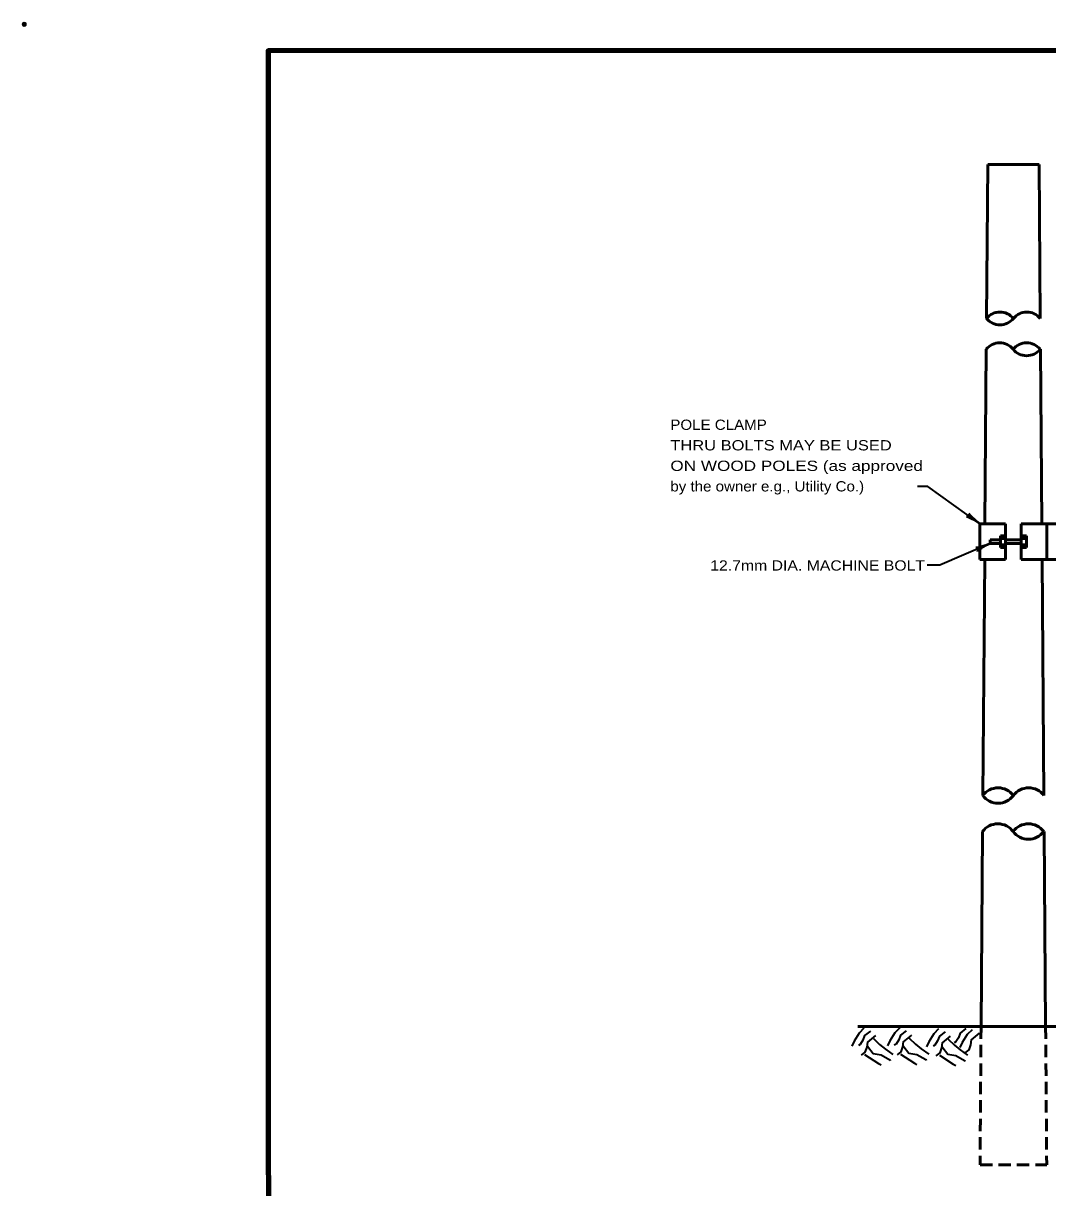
# Model space of a CAD drawing. Extents: x -421 to 434, y -46 to 498.
# Drawn here: x -421.4 to -181.8, y 225.9 to 498.2 of the extents above; entities that cross this region are included whole.
import ezdxf
from ezdxf.enums import TextEntityAlignment as Align

# ---------------------------------------------------------------- set-up
doc = ezdxf.new("R2010")
doc.units = 0
doc.header["$LTSCALE"] = 0.96
doc.header["$PDMODE"] = 32
doc.header["$PDSIZE"] = 0.48
doc.linetypes.add('MEDIUM_DASHED', pattern=[4.5, 3, -1.5])
doc.layers.add('1', color=7, linetype='Continuous', lineweight=53)

msp = doc.modelspace()

# ---------------------------------------------------------------- linework, layer by layer
at = {"layer": '1'}
for p, q in [((-195.7996, 465.1862), (-196.0765, 429.1862)), ((-195.7996, 465.1862), (-183.7996, 465.1862)), ((-183.7996, 465.1862), (-183.5226, 429.1862)), ((-196.1319, 421.9862), (-196.4457, 381.1862)), ((-183.4673, 421.9862), (-183.1534, 381.1862)), ((-191.6458, 381.1862), (-197.6458, 381.1862)), ((-197.6458, 381.1862), (-197.6458, 372.7862)), ((-191.6458, 381.1862), (-191.6458, 372.7862)), ((-187.9464, 381.1862), (-187.9464, 372.7862)), ((-187.9464, 381.1862), (-178.3464, 381.1862)), ((-181.9464, 381.1862), (-181.9464, 372.7862)), ((-192.8458, 377.4362), (-195.2458, 377.4362)), ((-195.2458, 377.4362), (-195.2458, 376.5362)), ((-192.8458, 376.5362), (-195.2458, 376.5362)), ((-192.8458, 378.3362), (-191.6458, 378.3362)), ((-192.8458, 378.3362), (-192.8458, 375.6362)), ((-192.8458, 377.7362), (-191.6458, 377.7362)), ((-192.8458, 376.2362), (-191.6458, 376.2362)), ((-187.9464, 377.4362), (-191.6458, 377.4362)), ((-187.9464, 376.5362), (-191.6458, 376.5362)), ((-186.7464, 378.3362), (-187.9464, 378.3362)), ((-186.7464, 377.7362), (-187.9464, 377.7362)), ((-186.7464, 376.2362), (-187.9464, 376.2362)), ((-186.7464, 378.3362), (-186.7464, 375.6362)), ((-192.8458, 375.6362), (-191.6458, 375.6362)), ((-186.7464, 375.6362), (-187.9464, 375.6362)), ((-191.6458, 372.7862), (-197.6458, 372.7862)), ((-196.5104, 372.7862), (-196.935, 317.5862)), ((-187.9464, 372.7862), (-178.3464, 372.7862)), ((-183.0888, 372.7862), (-182.6642, 317.5862)), ((-196.9996, 309.1862), (-197.3504, 263.5862)), ((-182.5996, 309.1862), (-182.2488, 263.5862)), ((-226.1504, 263.5862), (-149.8488, 263.5862))]:
    msp.add_line(p, q, dxfattribs=at)
at = {"layer": '1', "linetype": 'MEDIUM_DASHED'}
for p, q in [((-197.3504, 263.5862), (-197.5996, 231.1862)), ((-182.2488, 263.5862), (-181.9996, 231.1862)), ((-197.5996, 231.1862), (-181.9996, 231.1862))]:
    msp.add_line(p, q, dxfattribs=at)
at = {"layer": '1', "lineweight": 158}
msp.add_lwpolyline([(427.565, 491.8976), (-364.135, 491.7976), (-364.035, -34.2024)], dxfattribs=at)
at = {"layer": '1', "lineweight": 35}
for points in [[(-197.6458, 381.1862), (-209.7878, 389.8607), (-212.2577, 389.8607)], [(-195.2458, 376.5362), (-206.9651, 371.507), (-209.9642, 371.507)], [(-224.745, 263.1482), (-225.8618, 262.0311), (-227.0584, 260.1159), (-227.6168, 258.9988)], [(-223.2293, 262.5099), (-224.5855, 261.4725), (-224.9843, 260.3553), (-225.6225, 259.3978), (-226.0213, 259.1584)], [(-216.3691, 263.228), (-217.4859, 262.1109), (-218.6825, 260.1957), (-219.2409, 259.0786)], [(-214.8534, 262.5897), (-216.2096, 261.5523), (-216.6084, 260.4351), (-217.2466, 259.4776), (-217.6454, 259.2382)], [(-213.6569, 261.5523), (-215.5714, 259.9563), (-215.7309, 258.8392), (-216.1298, 257.6422), (-217.0073, 256.924)], [(-207.275, 262.9886), (-208.3918, 261.8715), (-209.5884, 259.9563), (-210.1468, 258.8392)], [(-205.7593, 262.3503), (-207.1155, 261.3129), (-207.5143, 260.1957), (-208.1525, 259.2382), (-208.5513, 258.9988)], [(-200.8931, 263.0685), (-202.2493, 262.0311), (-202.6481, 260.9139), (-203.2863, 259.9564), (-203.6851, 259.717)], [(-199.4573, 262.829), (-200.5741, 261.7119), (-201.7707, 259.7967), (-202.3291, 258.6796)], [(-197.7821, 262.0311), (-199.6966, 260.4351), (-199.8561, 259.318), (-200.255, 258.121), (-201.1325, 257.4028)], [(-222.0328, 261.4725), (-223.9473, 259.8765), (-224.1068, 258.7594), (-224.5057, 257.5624), (-225.3832, 256.8442)], [(-223.9473, 258.9988), (-222.5912, 257.2432), (-220.7564, 256.924), (-218.6823, 255.8069), (-218.6026, 255.5675)], [(-222.5114, 260.7543), (-221.0755, 259.3978), (-219.7194, 258.2806), (-217.9644, 257.0038)], [(-215.5714, 259.0786), (-214.2153, 257.323), (-212.3805, 257.0038), (-210.3064, 255.8867), (-210.2267, 255.6473)], [(-214.1355, 260.8341), (-212.6996, 259.4776), (-211.3435, 258.3604), (-209.5885, 257.0836)], [(-204.5628, 261.3129), (-206.4773, 259.7169), (-206.6368, 258.5998), (-207.0357, 257.4028), (-207.9132, 256.6846)], [(-206.4773, 258.8392), (-205.1212, 257.0836), (-203.2864, 256.7644), (-201.2123, 255.6473), (-201.1326, 255.4079)], [(-205.0414, 260.5947), (-203.6055, 259.2382), (-202.2494, 258.121), (-200.4944, 256.8442)], [(-224.5855, 257.0038), (-221.3148, 254.9291), (-220.7564, 254.6099)], [(-216.2096, 257.0836), (-212.9389, 255.0089), (-212.3805, 254.6897)], [(-207.1155, 256.8442), (-203.8448, 254.7695), (-203.2864, 254.4503)]]:
    msp.add_lwpolyline(points, dxfattribs=at)
at = {"layer": '1'}
for centre, radius, start, end in [((-192.9381, 426.6838), 4.0159, 38.6004, 141.3996), ((-186.6498, 426.6838), 4.0159, 38.6004, 141.3996), ((-192.9381, 431.6916), 4.0159, 218.6004, 321.3996), ((-192.9934, 419.4808), 4.0159, 38.6004, 141.3996), ((-186.7052, 419.4808), 4.0159, 38.6004, 141.3996), ((-186.7052, 424.4886), 4.0159, 218.6004, 321.3996), ((-193.3673, 314.9498), 4.4479, 36.66818, 143.33182), ((-186.2081, 314.9498), 4.4479, 36.66818, 143.33182), ((-193.3673, 320.2424), 4.4479, 216.66818, 323.33182), ((-193.4319, 306.53), 4.4479, 36.66818, 143.33182), ((-186.2727, 306.53), 4.4479, 36.66818, 143.33182), ((-186.2727, 311.8226), 4.4479, 216.66818, 323.33182)]:
    msp.add_arc(centre, radius, start, end, dxfattribs=at)
at = {"layer": '1', "lineweight": 40}
for centre, major_axis, ratio, start_param, end_param in [((-198.904, 381.6776), (1.8525, -1.0932), 0.122415, 0.89635335, 3.14159265), ((-198.904, 381.6776), (1.8525, -1.0932), 0.122415, 0.89635335, 3.14159265), ((-198.5923, 382.1744), (1.5925, -1.3968), 0.07063, 3.14071475, 5.41810995), ((-198.5923, 382.1744), (1.5925, -1.3968), 0.07063, 3.14071475, 5.41810995), ((-196.5816, 376.2393), (-2.02, -0.6375), 0.07063, 6.28230741, 8.55970261), ((-196.5816, 376.2393), (-2.02, -0.6375), 0.07063, 6.28230741, 8.55970261), ((-196.3184, 375.7151), (1.8953, 1.0172), 0.122415, 0.89635335, 3.14159265), ((-196.3184, 375.7151), (1.8953, 1.0172), 0.122415, 0.89635335, 3.14159265)]:
    msp.add_ellipse(centre, major_axis=major_axis, ratio=ratio, start_param=start_param, end_param=end_param, dxfattribs=at)
at = {"layer": '1'}
msp.add_point((-421.135, 497.9976), dxfattribs=at)

# ---------------------------------------------------------------- texts
for s, width, p in [('POLE CLAMP', 1.1, (-270.0325, 403.1282)), ('THRU BOLTS MAY BE USED', 1.2, (-270.0325, 398.3282)), ('ON WOOD POLES (as approved', 1.25, (-270.0325, 393.5282)), ('by the owner e.g., Utility Co.)', 1.1, (-270.0325, 388.7282))]:
    msp.add_text(s, height=2.4, dxfattribs=dict(at, width=width)).set_placement(p)
at = {"layer": '1', "width": 1.15}
msp.add_text('12.7mm DIA. MACHINE BOLT', height=2.4, dxfattribs=at).set_placement((-235.5813, 370.2158), align=Align.CENTER)

doc.saveas('drawing.dxf')
